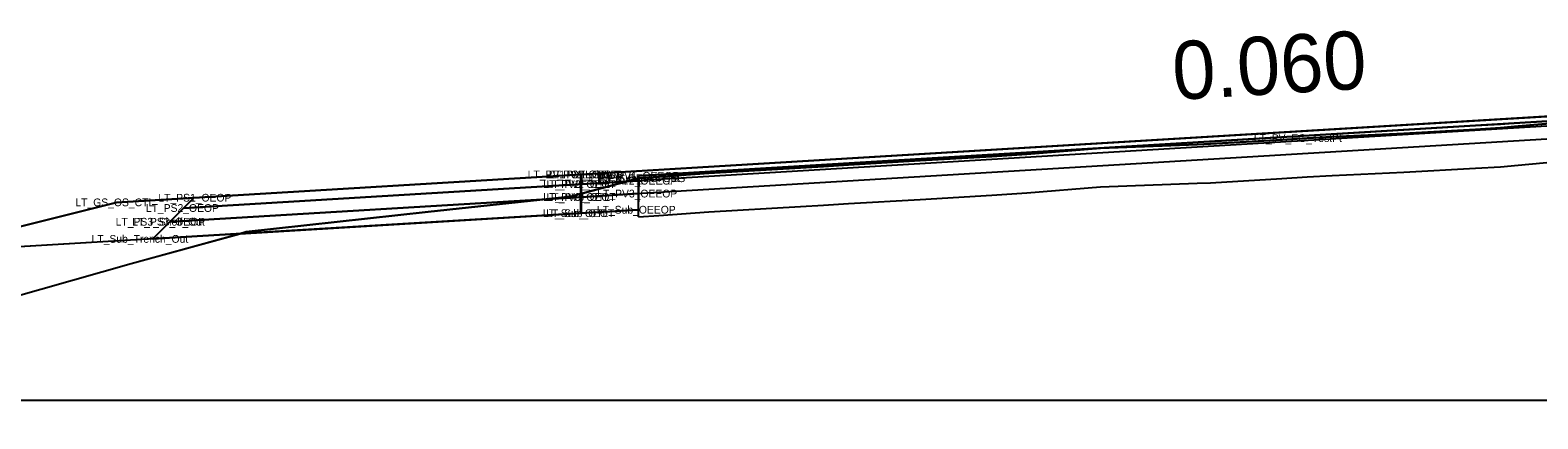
# Model space of a CAD drawing. Extents: x 2177029 to 2201446, y 59897 to 78390.
# Drawn here: x 2200162.49 to 2200201.45, y 65406.83 to 65416.86 of the extents above; entities that cross this region are included whole.
import ezdxf

# ---------------------------------------------------------------- set-up
doc = ezdxf.new("R2010")
doc.units = 0
for name, color, linetype in [('Exist Cross Section Cell', 7, 'Continuous'), ('Exist PHM Roadway Shape', 7, 'Continuous'), ('Exist XS Ground Line', 7, 'Continuous'), ('Old_Level_11', 7, 'Continuous'), ('Prop CMT Conc Surface', 7, 'Continuous'), ('Prop CMT Concrete Structures', 7, 'Continuous'), ('Prop CMT Guardrail Graphics', 7, 'Continuous'), ('Prop CMT Pvmt Course 1 CG', 7, 'Continuous'), ('Prop CMT Pvmt Course 2', 7, 'Continuous'), ('Prop CMT Pvmt Course 2 CG', 7, 'Continuous'), ('Prop CMT Pvmt Course 3', 7, 'Continuous'), ('Prop CMT Pvmt Course 4', 7, 'Continuous'), ('Prop CMT Pvmt Surface', 7, 'Continuous'), ('Prop CMT Pvmt Wedge Surface 1', 7, 'Continuous'), ('Prop CMT Slope Grass', 7, 'Continuous'), ('Prop CMT Subgrade Earthwork', 7, 'Continuous'), ('Prop Hatching', 7, 'Continuous'), ('Prop XS Side Slope Text', 7, 'Continuous'), ('Scratch_Level_0', 7, 'Continuous'), ('Scratch_Level_9', 7, 'Continuous')]:
    doc.layers.add(name, color=color, linetype=linetype)

msp = doc.modelspace()

# ---------------------------------------------------------------- linework, layer by layer
at = {"layer": 'Exist Cross Section Cell'}
msp.add_line((2200042.732, 65407.31), (2200242.732, 65407.31), dxfattribs=at)
at = {"layer": 'Exist XS Ground Line'}
msp.add_lwpolyline([(2200155.058, 65407.989), (2200165.104, 65410.838), (2200168.072, 65411.654), (2200172.777, 65412.176), (2200176.459, 65412.572), (2200177.807, 65412.928), (2200178.215, 65413.041), (2200178.735, 65413.078), (2200180.033, 65413.173), (2200182.402, 65413.311), (2200182.989, 65413.346), (2200183.638, 65413.385), (2200185.489, 65413.494), (2200187.339, 65413.601), (2200188.245, 65413.659), (2200190.15, 65413.815), (2200192.651, 65413.912), (2200192.989, 65413.924), (2200194.839, 65414.035), (2200195.489, 65414.077), (2200196.139, 65414.107), (2200197.989, 65414.197), (2200199.838, 65414.301), (2200200.489, 65414.338), (2200200.944, 65414.38), (2200201.961, 65414.473)], dxfattribs=at)
at = {"layer": 'Prop CMT Conc Surface'}
for points in [[(2200212.732, 65415.173), (2200178.215, 65413.102)], [(2200176.732, 65412.888), (2200176.732, 65413.138)], [(2200178.215, 65413.102), (2200178.215, 65412.977)], [(2200178.215, 65412.977), (2200176.732, 65412.888)]]:
    msp.add_lwpolyline(points, dxfattribs=at)
at = {"layer": 'Prop CMT Concrete Structures'}
for p, q in [((2200212.732, 65415.298), (2200176.732, 65413.138)), ((2200176.732, 65413.138), (2200176.722, 65413.137))]:
    msp.add_line(p, q, dxfattribs=at)
at = {"layer": 'Prop CMT Guardrail Graphics'}
for points in [[(2200212.732, 65414.715), (2200176.732, 65412.555)], [(2200176.732, 65412.555), (2200176.732, 65413.138)]]:
    msp.add_lwpolyline(points, dxfattribs=at)
at = {"layer": 'Prop CMT Pvmt Course 1 CG'}
for points in [[(2200176.722, 65412.554), (2200166.102, 65411.917)], [(2200176.722, 65412.137), (2200176.722, 65412.554)], [(2200165.658, 65411.474), (2200176.722, 65412.137)], [(2200166.102, 65411.917), (2200165.658, 65411.474)], [(2200166.102, 65411.917), (2200166.102, 65411.917)]]:
    msp.add_lwpolyline(points, dxfattribs=at)
at = {"layer": 'Prop CMT Pvmt Course 2'}
for points in [[(2200176.732, 65412.555), (2200176.722, 65412.554)], [(2200176.722, 65412.554), (2200176.722, 65412.137)], [(2200178.215, 65412.644), (2200176.732, 65412.555)], [(2200176.732, 65412.138), (2200176.732, 65412.555)], [(2200176.732, 65412.555), (2200176.732, 65412.138)], [(2200178.215, 65412.227), (2200178.215, 65412.644)], [(2200176.722, 65412.137), (2200176.732, 65412.138)], [(2200176.732, 65412.138), (2200178.215, 65412.227)]]:
    msp.add_lwpolyline(points, dxfattribs=at)
at = {"layer": 'Prop CMT Pvmt Course 2 CG'}
for points in [[(2200212.732, 65415.298), (2200176.732, 65413.138)], [(2200178.215, 65413.102), (2200212.732, 65415.173)], [(2200176.732, 65413.138), (2200176.723, 65413.138), (2200176.722, 65413.137)], [(2200176.722, 65413.137), (2200176.722, 65412.887)], [(2200176.732, 65412.888), (2200176.732, 65413.138)], [(2200176.732, 65413.138), (2200176.732, 65412.888)], [(2200178.215, 65412.977), (2200178.215, 65413.102)], [(2200176.722, 65412.887), (2200176.732, 65412.888)], [(2200176.732, 65412.888), (2200178.215, 65412.977)]]:
    msp.add_lwpolyline(points, dxfattribs=at)
at = {"layer": 'Prop CMT Pvmt Course 3'}
for points in [[(2200178.215, 65412.227), (2200178.229, 65413.041)], [(2200176.722, 65412.137), (2200165.658, 65411.474)], [(2200176.732, 65412.138), (2200176.722, 65412.137)], [(2200178.215, 65412.227), (2200176.732, 65412.138)], [(2200165.658, 65411.474), (2200159.459, 65411.102)]]:
    msp.add_lwpolyline(points, dxfattribs=at)
at = {"layer": 'Prop CMT Pvmt Course 4'}
msp.add_lwpolyline([(2200176.722, 65413.137), (2200166.722, 65412.537)], dxfattribs=at)
at = {"layer": 'Prop CMT Pvmt Surface'}
for points in [[(2200178.215, 65413.102), (2200178.735, 65413.134), (2200180.033, 65413.211), (2200180.276, 65413.226), (2200182.402, 65413.354), (2200182.989, 65413.389), (2200183.638, 65413.428), (2200185.489, 65413.539), (2200187.339, 65413.65), (2200187.989, 65413.689), (2200188.245, 65413.704), (2200190.15, 65413.819), (2200192.651, 65413.969), (2200192.989, 65413.989), (2200194.839, 65414.1), (2200195.489, 65414.139), (2200196.139, 65414.178), (2200197.989, 65414.289), (2200199.838, 65414.4), (2200200.489, 65414.439), (2200200.944, 65414.466), (2200201.961, 65414.527)], [(2200201.961, 65414.473), (2200200.944, 65414.38), (2200200.489, 65414.338), (2200199.838, 65414.301), (2200197.989, 65414.197), (2200196.139, 65414.107), (2200195.489, 65414.077), (2200194.839, 65414.035), (2200192.989, 65413.924), (2200192.651, 65413.912), (2200190.15, 65413.815), (2200188.245, 65413.659), (2200187.989, 65413.639), (2200187.339, 65413.601), (2200185.489, 65413.494), (2200183.638, 65413.385), (2200182.989, 65413.346), (2200182.402, 65413.311), (2200180.276, 65413.181), (2200180.033, 65413.173), (2200178.735, 65413.078), (2200178.215, 65413.041)], [(2200178.215, 65413.041), (2200178.215, 65413.102)]]:
    msp.add_lwpolyline(points, dxfattribs=at)
at = {"layer": 'Prop CMT Pvmt Wedge Surface 1'}
for p, q in [((2200200.944, 65413.38), (2200201.961, 65413.473)), ((2200194.839, 65413.035), (2200195.489, 65413.077)), ((2200195.489, 65413.077), (2200196.139, 65413.107)), ((2200196.139, 65413.107), (2200197.989, 65413.197)), ((2200197.989, 65413.197), (2200199.838, 65413.301)), ((2200199.838, 65413.301), (2200200.489, 65413.338)), ((2200200.489, 65413.338), (2200200.944, 65413.38)), ((2200178.215, 65412.041), (2200178.215, 65413.041)), ((2200187.339, 65412.601), (2200188.245, 65412.659)), ((2200188.245, 65412.659), (2200190.15, 65412.815)), ((2200190.15, 65412.815), (2200192.651, 65412.912)), ((2200192.651, 65412.912), (2200192.989, 65412.924)), ((2200192.989, 65412.924), (2200194.839, 65413.035)), ((2200180.033, 65412.173), (2200182.402, 65412.311)), ((2200182.402, 65412.311), (2200182.989, 65412.346)), ((2200182.989, 65412.346), (2200183.638, 65412.385)), ((2200183.638, 65412.385), (2200185.489, 65412.494)), ((2200185.489, 65412.494), (2200187.339, 65412.601)), ((2200178.215, 65412.041), (2200178.735, 65412.078)), ((2200178.735, 65412.078), (2200180.033, 65412.173))]:
    msp.add_line(p, q, dxfattribs=at)
at = {"layer": 'Prop CMT Slope Grass'}
for points in [[(2200176.732, 65412.888), (2200176.722, 65412.887)], [(2200176.722, 65412.887), (2200176.722, 65412.554)], [(2200178.215, 65412.977), (2200176.732, 65412.888)], [(2200176.732, 65412.555), (2200176.732, 65412.888)], [(2200176.732, 65412.888), (2200176.732, 65412.555)], [(2200178.215, 65412.644), (2200178.215, 65412.977)], [(2200176.722, 65412.554), (2200176.732, 65412.555)], [(2200176.732, 65412.555), (2200178.215, 65412.644)]]:
    msp.add_lwpolyline(points, dxfattribs=at)
at = {"layer": 'Prop CMT Subgrade Earthwork'}
for points in [[(2200212.732, 65415.048), (2200176.732, 65412.888)], [(2200176.732, 65412.888), (2200176.732, 65413.138)]]:
    msp.add_lwpolyline(points, dxfattribs=at)
at = {"layer": 'Prop Hatching'}
msp.add_lwpolyline([(2200166.722, 65412.537), (2200164.722, 65412.417), (2200142.374, 65406.83)], dxfattribs=at)
at = {"layer": 'Prop XS Side Slope Text'}
msp.add_lwpolyline([(2200201.961, 65414.473), (2200200.944, 65414.38), (2200200.489, 65414.338), (2200199.838, 65414.301), (2200197.989, 65414.197), (2200196.139, 65414.107), (2200195.489, 65414.077), (2200194.839, 65414.035), (2200192.989, 65413.924), (2200192.651, 65413.912), (2200190.15, 65413.815), (2200188.245, 65413.659), (2200187.339, 65413.601), (2200185.489, 65413.494), (2200183.638, 65413.385), (2200182.989, 65413.346), (2200182.402, 65413.311), (2200180.033, 65413.173), (2200178.735, 65413.078), (2200178.229, 65413.041), (2200177.807, 65412.928), (2200176.459, 65412.572), (2200172.777, 65412.176), (2200168.072, 65411.654), (2200167.911, 65411.609), (2200165.658, 65411.474), (2200159.463, 65411.103), (2200164.722, 65412.417), (2200166.722, 65412.537), (2200176.722, 65413.137), (2200212.732, 65415.298)], dxfattribs=at)
for points in [[(2200178.215, 65412.227), (2200178.229, 65413.041), (2200177.807, 65412.928), (2200176.459, 65412.572), (2200172.777, 65412.176), (2200168.072, 65411.654), (2200167.911, 65411.609), (2200176.732, 65412.138)], [(2200167.911, 65411.609), (2200165.658, 65411.474), (2200159.463, 65411.103), (2200147.458, 65408.101), (2200148.232, 65408.068), (2200155.058, 65407.989), (2200165.104, 65410.838)]]:
    msp.add_lwpolyline(points, close=True, dxfattribs=at)
at = {"layer": 'Scratch_Level_0'}
for points in [[(2200176.722, 65412.887), (2200166.456, 65412.271), (2200166.102, 65411.917)], [(2200176.722, 65412.554), (2200176.722, 65412.887)], [(2200166.102, 65411.917), (2200176.722, 65412.554)]]:
    msp.add_lwpolyline(points, dxfattribs=at)
at = {"layer": 'Scratch_Level_9'}
for points in [[(2200176.722, 65413.137), (2200166.722, 65412.537), (2200166.456, 65412.271)], [(2200176.722, 65412.887), (2200176.722, 65413.137)], [(2200166.456, 65412.271), (2200176.722, 65412.887)]]:
    msp.add_lwpolyline(points, dxfattribs=at)

# ---------------------------------------------------------------- texts
at = {"layer": 'Exist PHM Roadway Shape'}
for s, p in [('LT_PV_EG_TestPt', (2200194.115, 65413.975)), ('LT_PV1_OTL SE LB', (2200175.347, 65413.038)), ('LT_PV1_OEOT', (2200175.806, 65413.038)), ('LT_PV1_OTL', (2200175.893, 65413.037)), ('LT_PV_Sub_Tie_Out', (2200176.724, 65412.941)), ('LT_PV_OEEOP_EG', (2200176.969, 65412.94)), ('LT_PV2_OEEOP', (2200177.146, 65412.877)), ('LT_PV1_OEEOP', (2200177.202, 65413.002)), ('LT_PV2_OEOT', (2200175.749, 65412.788)), ('LT_PV3_OEOT', (2200175.749, 65412.455)), ('LT_PV2_OTL', (2200175.837, 65412.787)), ('LT_PV3_OTL', (2200175.837, 65412.454)), ('LT_PV3_OEEOP', (2200177.146, 65412.544)), ('LT_GS_OS_CTL', (2200163.659, 65412.317)), ('LT_PS2_OEOP', (2200165.48, 65412.171)), ('LT_PS1_OEOP', (2200165.803, 65412.437)), ('LT_Sub_OEEOP', (2200177.136, 65412.127)), ('LT_PS3_Shelf_Out', (2200164.7, 65411.817)), ('LT_PS3_OEOP', (2200165.125, 65411.817)), ('LT_Sub_OEOT', (2200175.74, 65412.038)), ('LT_Sub_OTL', (2200175.827, 65412.037)), ('LT_Sub_Trench_Out', (2200164.078, 65411.374))]:
    msp.add_text(s, height=0.2, dxfattribs=at).set_placement(p)
at = {"layer": 'Old_Level_11'}
msp.add_text('0.060', height=1.5, rotation=3.4337, dxfattribs=at).set_placement((2200192.051, 65415.059))

doc.saveas('drawing.dxf')
